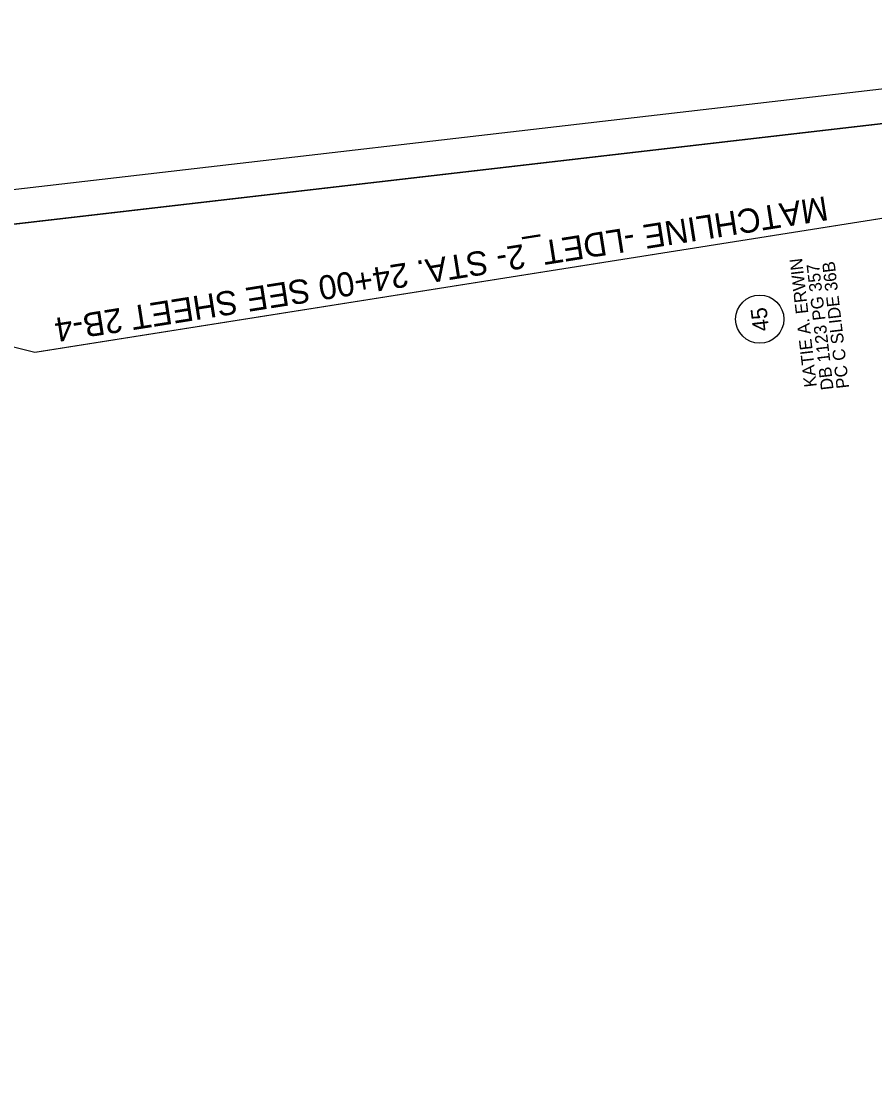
# Model space of a CAD drawing. Extents: x 477709 to 478991, y 494339 to 496137.
# Drawn here: x 478077 to 478502, y 495610 to 496137 of the extents above; entities that cross this region are included whole.
import ezdxf

# ---------------------------------------------------------------- set-up
doc = ezdxf.new("R2010")
doc.units = 0
for name, color, linetype in [('Default', 7, 'Continuous'), ('Matchline', 7, 'Continuous'), ('Matchline Text', 7, 'Continuous'), ('Prop Parcel Number CELL', 7, 'Continuous'), ('Sheet Layout Plan Border', 7, 'Continuous'), ('Sheet Plan CELL', 7, 'Continuous'), ('Sheet Plot Border Outside CELL', 7, 'Continuous')]:
    doc.layers.add(name, color=color, linetype=linetype)

msp = doc.modelspace()

# ---------------------------------------------------------------- linework, layer by layer
at = {"layer": 'Matchline'}
msp.add_line((478594.25, 496053.42), (478084.76, 495972.79), dxfattribs=at)
at = {"layer": 'Prop Parcel Number CELL'}
msp.add_line((478444.34, 495989.16), (478444.34, 495989.16), dxfattribs=at)
msp.add_circle((478444.34, 495989.16), 12, dxfattribs=at)
at = {"layer": 'Sheet Layout Plan Border'}
msp.add_lwpolyline([(478949.1, 494627.88), (478796.11, 495948.5), (478716.64, 495939.3), (478594.25, 496053.42), (478083.65, 495972.61), (477905.87, 496017.08), (477928.89, 495818.37), (477756.47, 495798.38), (477906.07, 494507.06)], close=True, dxfattribs=at)
at = {"layer": 'Sheet Plan CELL'}
for points in [[(477733.47, 495997.13), (477906.07, 494507.06), (478949.1, 494627.88), (478776.5, 496117.93)], [(478949.1, 494627.88), (477906.1, 494507.04), (477756.48, 495798.39), (477905.54, 495815.66), (477882.54, 496014.37), (478776.5, 496117.93)]]:
    msp.add_lwpolyline(points, close=True, dxfattribs=at)
at = {"layer": 'Sheet Plot Border Outside CELL'}
msp.add_lwpolyline([(478990.62, 494465.09), (478796.9, 496137.4), (477709.18, 496011.41), (477902.89, 494339.09)], close=True, dxfattribs=at)

# ---------------------------------------------------------------- texts
at = {"layer": 'Default'}
for s, p in [('KATIE A. ERWIN', (478472.77, 495955.67)), ('PC C SLIDE 36B', (478488.86, 495955)), ('DB 1123 PG 357', (478481.08, 495954.26))]:
    msp.add_text(s, height=6.25, rotation=96.6074, dxfattribs=at).set_placement(p)
at = {"layer": 'Matchline Text'}
msp.add_text('MATCHLINE -LDET_2- STA. 24+00 SEE SHEET 2B-4', height=12, rotation=188.9925, dxfattribs=at).set_placement((478477.21, 496050.41))
at = {"layer": 'Prop Parcel Number CELL'}
msp.add_text('45', height=8, rotation=96.5773, dxfattribs=at).set_placement((478449.02, 495983.56))

doc.saveas('drawing.dxf')
